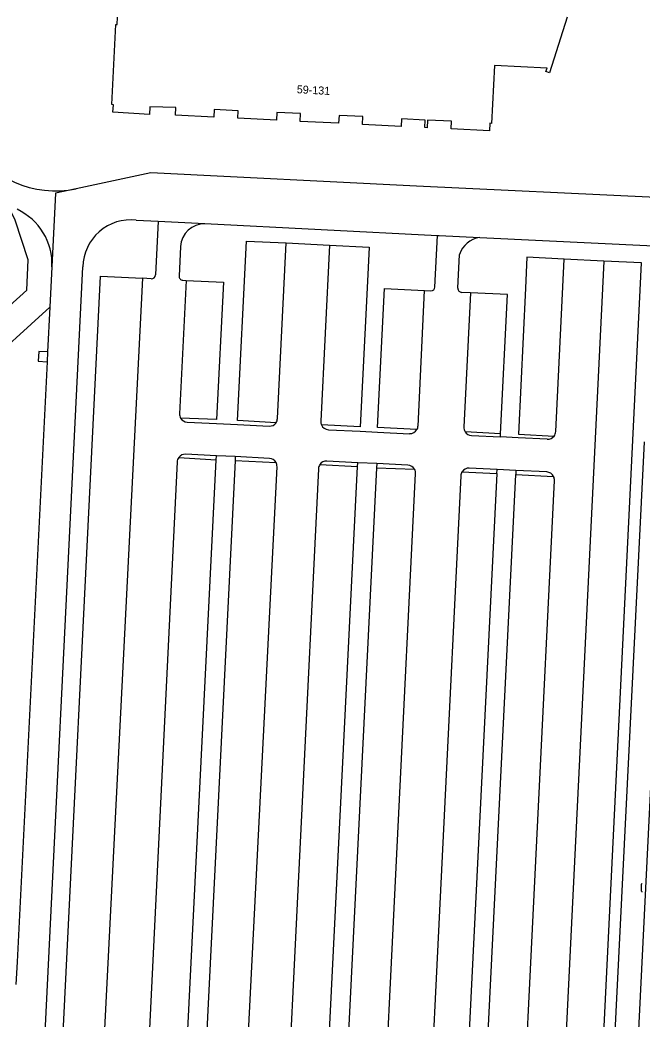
# Model space of a CAD drawing. Extents: x 161761 to 162722, y 384793 to 385405.
# Drawn here: x 162039.8 to 162117.4, y 385124.9 to 385249.7 of the extents above; entities that cross this region are included whole.
import ezdxf

# ---------------------------------------------------------------- set-up
doc = ezdxf.new("R2010")
doc.units = 0
for name, color, linetype in [('IMGEO_Kolk', 7, 'Continuous'), ('IMGEO_Pand', 7, 'Continuous'), ('IMGEO_Pand_nummerreeks', 7, 'Continuous'), ('IMGEO_Parkeervlak_open', 7, 'Continuous'), ('IMGEO_Rijbaan_lokaal_gesloten', 7, 'Continuous'), ('IMGEO_Rijbaan_lokaal_open', 7, 'Continuous'), ('IMGEO_Voetpad_open', 7, 'Continuous')]:
    doc.layers.add(name, color=color, linetype=linetype)

msp = doc.modelspace()

# ---------------------------------------------------------------- linework, layer by layer
at = {"layer": 'IMGEO_Kolk'}
msp.add_line((162117.36, 385140.86), (162117.36, 385141.71), dxfattribs=at)
msp.add_lwpolyline([(162117.36, 385140.86), (162117.36, 385141.71)], dxfattribs=at)
for centre, start, end in [((162117.44, 385141.71), 91.552, 178.448), ((162117.44, 385141.71), 91.552, 178.448), ((162117.44, 385140.86), 181.552, 268.448), ((162117.44, 385140.86), 181.552, 268.448)]:
    msp.add_arc(centre, 0.0765, start, end, dxfattribs=at)
at = {"layer": 'IMGEO_Pand'}
msp.add_lwpolyline([(162108.1, 385250), (162105.87, 385243.04), (162105.42, 385243.22), (162105.58, 385243.65), (162099, 385243.98), (162098.65, 385236.75), (162098.44, 385236.77), (162098.4, 385235.81), (162093.58, 385236.05), (162093.63, 385237.01), (162090.66, 385237.16), (162090.62, 385236.2), (162090.32, 385236.22), (162090.36, 385237.16), (162087.39, 385237.32), (162087.34, 385236.37), (162082.53, 385236.62), (162082.57, 385237.59), (162079.6, 385237.71), (162079.55, 385236.76), (162074.73, 385237), (162074.77, 385237.97), (162071.83, 385238.09), (162071.79, 385237.15), (162066.96, 385237.39), (162067.01, 385238.33), (162064.01, 385238.47), (162063.96, 385237.53), (162059.16, 385237.78), (162059.21, 385238.72), (162055.96, 385238.82), (162055.93, 385237.87), (162051.36, 385238.14), (162051.42, 385239.07), (162051.22, 385239.1), (162051.71, 385249.1), (162051.88, 385249.1), (162051.93, 385250)], dxfattribs=at)
at = {"layer": 'IMGEO_Parkeervlak_open'}
for points in [[(162071.73, 385199.36), (162066.93, 385199.62), (162068.03, 385222.05), (162072.98, 385221.81)], [(162078.39, 385221.54), (162083.34, 385221.3), (162083.09, 385216.22), (162082.24, 385198.84), (162077.39, 385199.1)], [(162107.72, 385219.79), (162103.07, 385220.02), (162102.88, 385216.16), (162101.99, 385197.91), (162106.45, 385197.69)], [(162105.03, 385063.63), (162109.74, 385063.48), (162117.38, 385219.31), (162112.67, 385219.54)], [(162048.31, 385105.21), (162045.34, 385105.36), (162045.15, 385105.37), (162044.27, 385105.42), (162049.8, 385217.66), (162055.05, 385217.4)], [(162060.49, 385217.13), (162065.15, 385216.9), (162064.31, 385199.75), (162059.81, 385199.94)], [(162089.33, 385198.5), (162084.41, 385198.77), (162085.26, 385216.11), (162090.28, 385215.86)], [(162099.77, 385197.99), (162100.62, 385215.36), (162096.01, 385215.58)], [(162059.77, 385104.29), (162064.27, 385194.74)], [(162066.61, 385194.63), (162062.12, 385104.16)], [(162077.42, 385103.21), (162081.92, 385193.88)], [(162084.27, 385193.74), (162079.77, 385103.1)], [(162099.31, 385193.01), (162094.81, 385102.36)], [(162097.16, 385102.22), (162101.66, 385192.88)]]:
    msp.add_lwpolyline(points, dxfattribs=at)
at = {"layer": 'IMGEO_Rijbaan_lokaal_gesloten'}
msp.add_lwpolyline([(162121.8, 385220.49), (162113.46, 385051.84)], dxfattribs=at)
at = {"layer": 'IMGEO_Rijbaan_lokaal_open'}
for points in [[(162046.78, 385228.58), (162044.2, 385228.02), (162043.74, 385218.82)], [(162057.02, 385224.52), (162056.68, 385217.82)], [(162057.02, 385224.52), (162062.84, 385224.23)], [(162091.58, 385216.3), (162091.9, 385222.76)], [(162091.9, 385222.76), (162092.09, 385222.75), (162097.16, 385222.5)], [(162071.91, 385199.88), (162072.98, 385221.81)], [(162072.98, 385221.81), (162078.39, 385221.54)], [(162078.39, 385221.54), (162077.31, 385199.54)], [(162059.8, 385221.38), (162059.61, 385217.67)], [(162094.43, 385216.16), (162094.63, 385220.36)], [(162112.67, 385219.54), (162105.03, 385063.63)], [(162106.66, 385198.26), (162107.72, 385219.79)], [(162112.67, 385219.54), (162107.72, 385219.79)], [(162055.05, 385217.4), (162049.36, 385104.7)], [(162056.15, 385217.34), (162055.05, 385217.4)], [(162060.49, 385217.13), (162059.68, 385200.48)], [(162060.09, 385217.15), (162060.49, 385217.13)], [(162089.46, 385198.94), (162090.28, 385215.86)], [(162090.28, 385215.86), (162091.05, 385215.83)], [(162096.01, 385215.58), (162094.9, 385215.64)], [(162096.01, 385215.58), (162095.18, 385198.82)], [(162060.63, 385199.43), (162064.28, 385199.25), (162066.91, 385199.13), (162070.86, 385198.93)], [(162078.26, 385198.49), (162082.22, 385198.3), (162084.38, 385198.19), (162088.41, 385197.99)], [(162096.13, 385197.77), (162099.75, 385197.6)], [(162105.61, 385197.31), (162101.97, 385197.49), (162099.75, 385197.6)], [(162064.29, 385195.23), (162060.43, 385195.42)], [(162059.38, 385194.47), (162054.99, 385104.92)], [(162066.64, 385195.12), (162064.29, 385195.23)], [(162070.9, 385194.91), (162066.64, 385195.12)], [(162081.95, 385194.37), (162078.07, 385194.56)], [(162084.3, 385194.25), (162081.95, 385194.37)], [(162088.2, 385194.06), (162084.3, 385194.25)], [(162067.33, 385104.3), (162071.85, 385193.86)], [(162077.02, 385193.61), (162072.61, 385103.67)], [(162084.74, 385103.08), (162089.15, 385193.01)], [(162099.34, 385193.52), (162095.85, 385193.69)], [(162101.69, 385193.4), (162099.34, 385193.52)], [(162105.55, 385193.21), (162101.69, 385193.4)], [(162094.8, 385192.74), (162090.39, 385102.8)], [(162102.09, 385102.23), (162106.5, 385192.16)]]:
    msp.add_lwpolyline(points, dxfattribs=at)
for centre, radius, start, end in [((162044.19, 385240.89), 12.58, 210.1487, 281.8576), ((162036.2, 385219.17), 7.55, 357.386, 65.0628), ((162062.8, 385221.22), 3, 89.244, 177.0607), ((162097.68, 385219.32), 3.22, 99.4368, 161.1458), ((162056.17, 385217.85), 0.505, 267.7544, 356.5094), ((162060.11, 385217.65), 0.499, 176.9571, 267.3181), ((162091.08, 385216.33), 0.5, 267.1369, 357.1268), ((162094.93, 385216.14), 0.499, 177.1858, 267.3071), ((162060.67, 385200.43), 0.993, 177.0092, 209.46), ((162060.68, 385200.43), 0.997, 209.3025, 267.2649), ((162070.91, 385199.93), 1, 267.2313, 324.9443), ((162070.91, 385199.93), 0.998, 324.9271, 357.1565), ((162078.32, 385199.49), 1.01, 177.3282, 202.5371), ((162078.31, 385199.49), 1, 202.6886, 267.134), ((162088.45, 385199), 1, 267.3236, 330.4891), ((162088.46, 385198.99), 0.997, 330.502, 357.1968), ((162096.17, 385198.77), 0.989, 176.9702, 212.8806), ((162096.18, 385198.77), 1, 212.7639, 267.2187), ((162105.67, 385198.31), 0.994, 321.5876, 357.3223), ((162105.66, 385198.3), 0.997, 267.0909, 321.7867), ((162060.38, 385194.43), 0.996, 87.0375, 144.0447), ((162060.39, 385194.42), 1.01, 144.146, 177.0184), ((162070.85, 385193.91), 1, 28.808, 87.1688), ((162070.84, 385193.91), 1.01, 357.3396, 28.6968), ((162078.02, 385193.56), 0.996, 143.7231, 177.2642), ((162078.02, 385193.56), 1, 87.2064, 143.7619), ((162088.15, 385193.06), 0.999, 29.2867, 87.2422), ((162088.16, 385193.06), 0.992, 357.0512, 29.4654), ((162095.8, 385192.69), 1, 147.9359, 177.1265), ((162095.8, 385192.69), 0.998, 87.1648, 147.9452), ((162105.5, 385192.21), 0.996, 25.9665, 87.3719), ((162105.5, 385192.21), 0.999, 357.0912, 26.024)]:
    msp.add_arc(centre, radius, start, end, dxfattribs=at)
at = {"layer": 'IMGEO_Voetpad_open'}
for points in [[(162119.21, 385227.48), (162089.27, 385228.91), (162056.08, 385230.58), (162046.78, 385228.58)], [(162031.04, 385207.3), (162040.59, 385215.92), (162040.78, 385219.71), (162039.13, 385224.67), (162038.29, 385226.51)], [(162054.26, 385224.66), (162057.02, 385224.52)], [(162062.84, 385224.23), (162091.9, 385222.76)], [(162097.16, 385222.5), (162118.91, 385221.44)], [(162041.98, 385104.58), (162047.62, 385218.82)], [(162043.74, 385218.82), (162043.48, 385213.78)], [(162034.55, 385205.7), (162043.48, 385213.78)], [(162043.48, 385213.78), (162043.2, 385208.2)], [(162043.2, 385208.2), (162042.09, 385208.25), (162042.03, 385207.03), (162043.14, 385206.97)], [(162043.2, 385208.2), (162043.14, 385206.97)], [(162043.14, 385206.97), (162039.38, 385132.01), (162039.22, 385129.2)], [(162099.77, 385197.99), (162095.34, 385198.23)], [(162099.75, 385197.6), (162099.77, 385197.99)], [(162117.7, 385196.98), (162110.96, 385061.29)], [(162059.57, 385195.01), (162064.27, 385194.74)], [(162064.27, 385194.74), (162064.29, 385195.23)], [(162066.64, 385195.12), (162066.61, 385194.63)], [(162066.61, 385194.63), (162071.73, 385194.39)], [(162077.21, 385194.15), (162081.92, 385193.88)], [(162081.92, 385193.88), (162081.95, 385194.37)], [(162084.3, 385194.25), (162084.27, 385193.74)], [(162084.27, 385193.74), (162089.02, 385193.55)], [(162094.95, 385193.22), (162099.31, 385193.01)], [(162099.31, 385193.01), (162099.34, 385193.52)], [(162101.69, 385193.4), (162101.66, 385192.88)], [(162101.66, 385192.88), (162106.4, 385192.65)]]:
    msp.add_lwpolyline(points, dxfattribs=at)
msp.add_arc((162053.57, 385218.75), 5.95, 83.3807, 179.2642, dxfattribs=at)

# ---------------------------------------------------------------- texts
at = {"layer": 'IMGEO_Pand_nummerreeks'}
msp.add_text('59-131', height=1, rotation=356.8899, dxfattribs=at).set_placement((162074.3, 385240.52))

doc.saveas('drawing.dxf')
